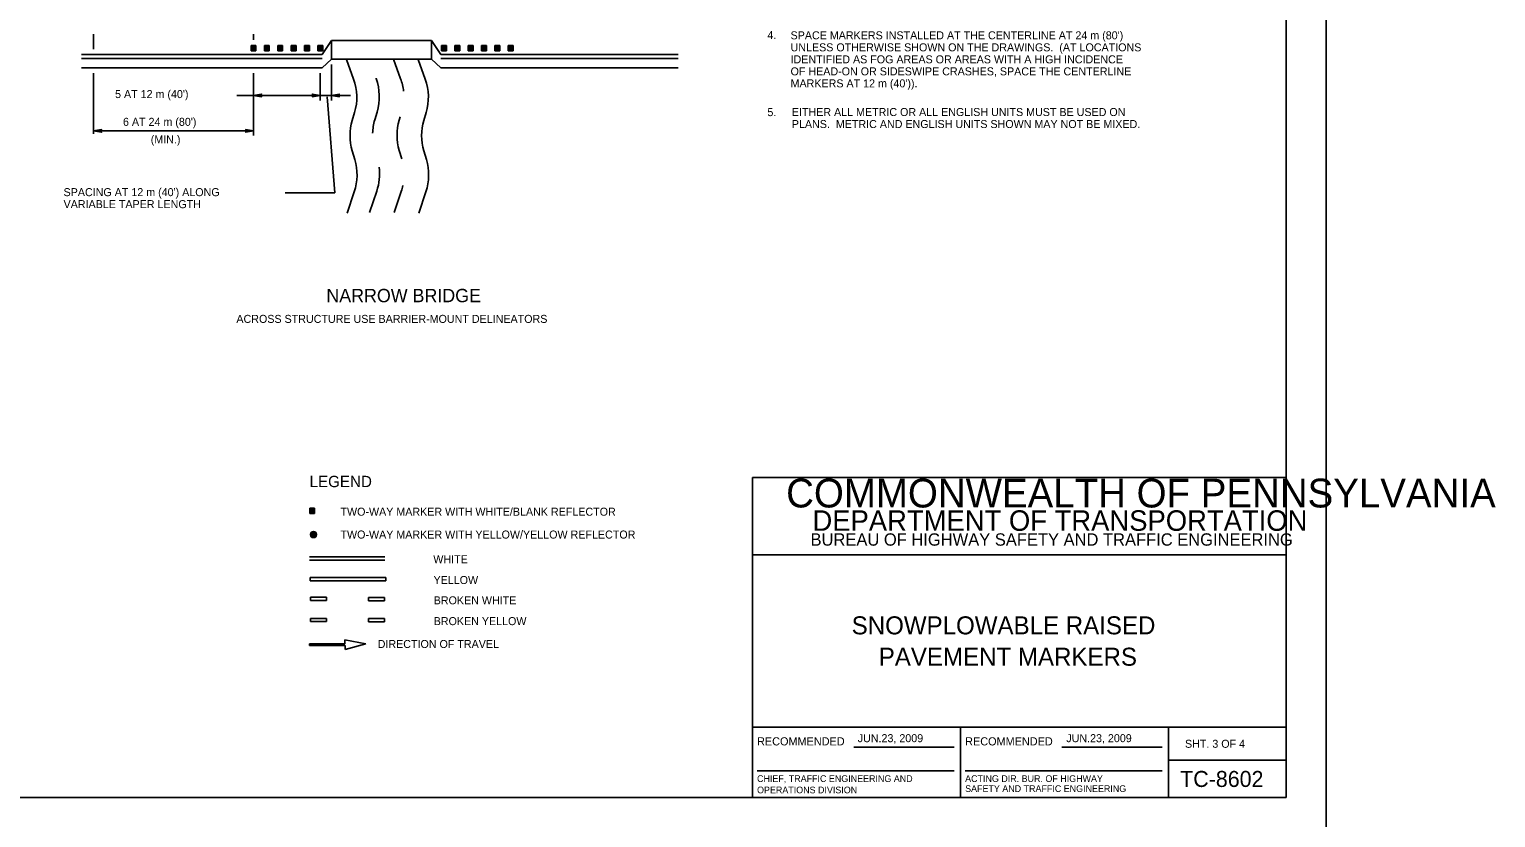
# Model space of a CAD drawing. Extents: x 639362 to 641108, y 298458 to 299646.
# Drawn here: x 640558 to 641108, y 299059 to 299355 of the extents above; entities that cross this region are included whole.
import ezdxf

# ---------------------------------------------------------------- set-up
doc = ezdxf.new("R2010")
doc.units = 0
for name, color, linetype in [('1', 7, 'Continuous'), ('2', 7, 'Continuous'), ('3', 7, 'Continuous'), ('PLT-BNDY', 7, 'Continuous')]:
    doc.layers.add(name, color=color, linetype=linetype)

# ---------------------------------------------------------------- blocks, each defined once
blk = doc.blocks.new('RARROW')
at = {"layer": '3'}
blk.add_lwpolyline([(-2.2695, 0.285), (-2.184875, 0.12075), (0, 0), (-2.2695, 0.285), (-2.38575, 0.384625), (0, 0), (-2.183125, -0.108), (-2.262875, -0.2705), (0, 0), (-2.38575, -0.379125), (-2.262875, -0.2705)], dxfattribs=at)

msp = doc.modelspace()

# ---------------------------------------------------------------- linework, layer by layer
at = {"layer": '1'}
for p, q in [((641029.31, 299066.63), (641029.31, 299630.63)), ((640829.31, 299066.63), (640829.31, 299186.63)), ((640829.31, 299186.63), (641029.31, 299186.63)), ((641029.31, 299157.63), (640829.31, 299157.63)), ((640829.31, 299093), (641029.31, 299093)), ((640907.31, 299093), (640907.31, 299066.63)), ((640985.19, 299066.63), (640985.19, 299093)), ((640867.24, 299085.57), (640904.87, 299085.57)), ((640945.24, 299085.57), (640982.87, 299085.57)), ((640985.19, 299080.63), (641029.31, 299080.63)), ((640830.99, 299076.68), (640904.87, 299076.68)), ((640908.99, 299076.68), (640982.87, 299076.68)), ((641029.31, 299066.63), (640243.31, 299066.63)), ((640243.31, 299066.63), (640829.31, 299066.63))]:
    msp.add_line(p, q, dxfattribs=at)
at = {"layer": '2'}
for p, q in [((640582.27, 299347.07), (640582.27, 299352.76)), ((640641.38, 299348.5), (640643.16, 299348.5)), ((640641.38, 299346.46), (640641.38, 299348.5)), ((640641.56, 299348.32), (640642.98, 299348.32)), ((640641.56, 299346.63), (640641.56, 299348.32)), ((640641.74, 299348.14), (640642.8, 299348.14)), ((640641.74, 299346.81), (640641.74, 299348.14)), ((640641.91, 299346.99), (640641.91, 299347.96)), ((640641.91, 299347.96), (640642.62, 299347.96)), ((640642.09, 299347.79), (640642.45, 299347.79)), ((640642.09, 299347.17), (640642.09, 299347.79)), ((640642.27, 299350.54), (640642.27, 299352.76)), ((640642.27, 299347.61), (640642.27, 299347.34)), ((640642.45, 299347.79), (640642.45, 299347.17)), ((640642.62, 299347.96), (640642.62, 299346.99)), ((640642.8, 299348.14), (640642.8, 299346.81)), ((640642.98, 299348.32), (640642.98, 299346.63)), ((640643.16, 299348.5), (640643.16, 299346.46)), ((640646.38, 299348.5), (640648.16, 299348.5)), ((640646.38, 299346.46), (640646.38, 299348.5)), ((640646.56, 299348.32), (640647.98, 299348.32)), ((640646.56, 299346.63), (640646.56, 299348.32)), ((640646.74, 299348.14), (640647.8, 299348.14)), ((640646.74, 299346.81), (640646.74, 299348.14)), ((640646.91, 299346.99), (640646.91, 299347.96)), ((640646.91, 299347.96), (640647.62, 299347.96)), ((640647.09, 299347.79), (640647.45, 299347.79)), ((640647.09, 299347.17), (640647.09, 299347.79)), ((640647.27, 299347.61), (640647.27, 299347.34)), ((640647.45, 299347.79), (640647.45, 299347.17)), ((640647.62, 299347.96), (640647.62, 299346.99)), ((640647.8, 299348.14), (640647.8, 299346.81)), ((640647.98, 299348.32), (640647.98, 299346.63)), ((640648.16, 299348.5), (640648.16, 299346.46)), ((640651.38, 299348.49), (640653.16, 299348.49)), ((640651.38, 299346.45), (640651.38, 299348.49)), ((640651.56, 299348.32), (640652.98, 299348.32)), ((640651.56, 299346.63), (640651.56, 299348.32)), ((640651.74, 299348.14), (640652.8, 299348.14)), ((640651.74, 299346.81), (640651.74, 299348.14)), ((640651.91, 299346.99), (640651.91, 299347.96)), ((640651.91, 299347.96), (640652.62, 299347.96)), ((640652.09, 299347.79), (640652.45, 299347.79)), ((640652.09, 299347.16), (640652.09, 299347.79)), ((640652.27, 299347.61), (640652.27, 299347.34)), ((640652.45, 299347.79), (640652.45, 299347.16)), ((640652.62, 299347.96), (640652.62, 299346.99)), ((640652.8, 299348.14), (640652.8, 299346.81)), ((640652.98, 299348.32), (640652.98, 299346.63)), ((640653.16, 299348.49), (640653.16, 299346.45)), ((640656.38, 299348.49), (640658.16, 299348.49)), ((640656.38, 299346.45), (640656.38, 299348.49)), ((640656.56, 299348.31), (640657.98, 299348.31)), ((640656.56, 299346.63), (640656.56, 299348.31)), ((640656.74, 299348.14), (640657.8, 299348.14)), ((640656.74, 299346.81), (640656.74, 299348.14)), ((640656.91, 299346.99), (640656.91, 299347.96)), ((640656.91, 299347.96), (640657.62, 299347.96)), ((640657.09, 299347.78), (640657.45, 299347.78)), ((640657.09, 299347.16), (640657.09, 299347.78)), ((640657.27, 299347.61), (640657.27, 299347.34)), ((640657.45, 299347.78), (640657.45, 299347.16)), ((640657.62, 299347.96), (640657.62, 299346.99)), ((640657.8, 299348.14), (640657.8, 299346.81)), ((640657.98, 299348.31), (640657.98, 299346.63)), ((640658.16, 299348.49), (640658.16, 299346.45)), ((640661.38, 299348.49), (640663.16, 299348.49)), ((640661.38, 299346.45), (640661.38, 299348.49)), ((640661.56, 299348.31), (640662.98, 299348.31)), ((640661.56, 299346.63), (640661.56, 299348.31)), ((640661.74, 299348.14), (640662.8, 299348.14)), ((640661.74, 299346.81), (640661.74, 299348.14)), ((640661.91, 299346.98), (640661.91, 299347.96)), ((640661.91, 299347.96), (640662.62, 299347.96)), ((640662.09, 299347.78), (640662.45, 299347.78)), ((640662.09, 299347.16), (640662.09, 299347.78)), ((640662.27, 299347.61), (640662.27, 299347.34)), ((640662.45, 299347.78), (640662.45, 299347.16)), ((640662.62, 299347.96), (640662.62, 299346.98)), ((640662.8, 299348.14), (640662.8, 299346.81)), ((640662.98, 299348.31), (640662.98, 299346.63)), ((640663.16, 299348.49), (640663.16, 299346.45)), ((640666.38, 299348.49), (640668.16, 299348.49)), ((640666.38, 299346.45), (640666.38, 299348.49)), ((640666.56, 299348.31), (640667.98, 299348.31)), ((640666.56, 299346.63), (640666.56, 299348.31)), ((640666.74, 299348.13), (640667.8, 299348.13)), ((640666.74, 299346.81), (640666.74, 299348.13)), ((640666.91, 299346.98), (640666.91, 299347.96)), ((640666.91, 299347.96), (640667.62, 299347.96)), ((640667.09, 299347.78), (640667.45, 299347.78)), ((640667.09, 299347.16), (640667.09, 299347.78)), ((640667.27, 299347.61), (640667.27, 299347.34)), ((640667.45, 299347.78), (640667.45, 299347.16)), ((640667.62, 299347.96), (640667.62, 299346.98)), ((640667.8, 299348.13), (640667.8, 299346.81)), ((640667.94, 299345.07), (640671.45, 299350.34)), ((640667.98, 299348.31), (640667.98, 299346.63)), ((640668.16, 299348.49), (640668.16, 299346.45)), ((640671.45, 299350.34), (640708.95, 299350.34)), ((640671.45, 299350.34), (640671.45, 299343.31)), ((640712.47, 299345.07), (640708.95, 299350.34)), ((640708.95, 299350.34), (640708.95, 299343.31)), ((640712.75, 299348.49), (640714.52, 299348.49)), ((640712.75, 299346.45), (640712.75, 299348.49)), ((640712.92, 299348.31), (640714.34, 299348.31)), ((640712.92, 299346.63), (640712.92, 299348.31)), ((640713.1, 299348.13), (640714.17, 299348.13)), ((640713.1, 299346.81), (640713.1, 299348.13)), ((640713.28, 299346.98), (640713.28, 299347.96)), ((640713.28, 299347.96), (640713.99, 299347.96)), ((640713.46, 299347.78), (640713.81, 299347.78)), ((640713.46, 299347.16), (640713.46, 299347.78)), ((640713.63, 299347.61), (640713.63, 299347.34)), ((640713.81, 299347.78), (640713.81, 299347.16)), ((640713.99, 299347.96), (640713.99, 299346.98)), ((640714.17, 299348.13), (640714.17, 299346.81)), ((640714.34, 299348.31), (640714.34, 299346.63)), ((640714.52, 299348.49), (640714.52, 299346.45)), ((640717.75, 299348.49), (640719.52, 299348.49)), ((640717.75, 299346.45), (640717.75, 299348.49)), ((640717.92, 299348.31), (640719.34, 299348.31)), ((640717.92, 299346.63), (640717.92, 299348.31)), ((640718.1, 299348.13), (640719.17, 299348.13)), ((640718.1, 299346.81), (640718.1, 299348.13)), ((640718.28, 299346.98), (640718.28, 299347.96)), ((640718.28, 299347.96), (640718.99, 299347.96)), ((640718.46, 299347.78), (640718.81, 299347.78)), ((640718.46, 299347.16), (640718.46, 299347.78)), ((640718.63, 299347.6), (640718.63, 299347.34)), ((640718.81, 299347.78), (640718.81, 299347.16)), ((640718.99, 299347.96), (640718.99, 299346.98)), ((640719.17, 299348.13), (640719.17, 299346.81)), ((640719.34, 299348.31), (640719.34, 299346.63)), ((640719.52, 299348.49), (640719.52, 299346.45)), ((640722.75, 299348.49), (640724.52, 299348.49)), ((640722.75, 299346.45), (640722.75, 299348.49)), ((640722.92, 299348.31), (640724.34, 299348.31)), ((640722.92, 299346.63), (640722.92, 299348.31)), ((640723.1, 299348.13), (640724.17, 299348.13)), ((640723.1, 299346.8), (640723.1, 299348.13)), ((640723.28, 299346.98), (640723.28, 299347.96)), ((640723.28, 299347.96), (640723.99, 299347.96)), ((640723.46, 299347.78), (640723.81, 299347.78)), ((640723.46, 299347.16), (640723.46, 299347.78)), ((640723.63, 299347.6), (640723.63, 299347.33)), ((640723.81, 299347.78), (640723.81, 299347.16)), ((640723.99, 299347.96), (640723.99, 299346.98)), ((640724.17, 299348.13), (640724.17, 299346.8)), ((640724.34, 299348.31), (640724.34, 299346.63)), ((640724.52, 299348.49), (640724.52, 299346.45)), ((640727.75, 299348.49), (640729.52, 299348.49)), ((640727.75, 299346.45), (640727.75, 299348.49)), ((640727.92, 299348.31), (640729.34, 299348.31)), ((640727.92, 299346.62), (640727.92, 299348.31)), ((640728.1, 299348.13), (640729.17, 299348.13)), ((640728.1, 299346.8), (640728.1, 299348.13)), ((640728.28, 299346.98), (640728.28, 299347.95)), ((640728.28, 299347.95), (640728.99, 299347.95)), ((640728.46, 299347.78), (640728.81, 299347.78)), ((640728.46, 299347.16), (640728.46, 299347.78)), ((640728.63, 299347.6), (640728.63, 299347.33)), ((640728.81, 299347.78), (640728.81, 299347.16)), ((640728.99, 299347.95), (640728.99, 299346.98)), ((640729.17, 299348.13), (640729.17, 299346.8)), ((640729.34, 299348.31), (640729.34, 299346.62)), ((640729.52, 299348.49), (640729.52, 299346.45)), ((640732.75, 299348.49), (640734.52, 299348.49)), ((640732.75, 299346.45), (640732.75, 299348.49)), ((640732.92, 299348.31), (640734.34, 299348.31)), ((640732.92, 299346.62), (640732.92, 299348.31)), ((640733.1, 299348.13), (640734.17, 299348.13)), ((640733.1, 299346.8), (640733.1, 299348.13)), ((640733.28, 299346.98), (640733.28, 299347.95)), ((640733.28, 299347.95), (640733.99, 299347.95)), ((640733.46, 299347.78), (640733.81, 299347.78)), ((640733.46, 299347.16), (640733.46, 299347.78)), ((640733.63, 299347.6), (640733.63, 299347.33)), ((640733.81, 299347.78), (640733.81, 299347.16)), ((640733.99, 299347.95), (640733.99, 299346.98)), ((640734.17, 299348.13), (640734.17, 299346.8)), ((640734.34, 299348.31), (640734.34, 299346.62)), ((640734.52, 299348.49), (640734.52, 299346.45)), ((640737.75, 299348.48), (640739.52, 299348.48)), ((640737.75, 299346.44), (640737.75, 299348.48)), ((640737.92, 299348.31), (640739.34, 299348.31)), ((640737.92, 299346.62), (640737.92, 299348.31)), ((640738.1, 299348.13), (640739.17, 299348.13)), ((640738.1, 299346.8), (640738.1, 299348.13)), ((640738.28, 299346.98), (640738.28, 299347.95)), ((640738.28, 299347.95), (640738.99, 299347.95)), ((640738.46, 299347.78), (640738.81, 299347.78)), ((640738.46, 299347.15), (640738.46, 299347.78)), ((640738.63, 299347.6), (640738.63, 299347.33)), ((640738.81, 299347.78), (640738.81, 299347.15)), ((640738.99, 299347.95), (640738.99, 299346.98)), ((640739.17, 299348.13), (640739.17, 299346.8)), ((640739.34, 299348.31), (640739.34, 299346.62)), ((640739.52, 299348.48), (640739.52, 299346.44)), ((640577.74, 299345.07), (640667.94, 299345.07)), ((640577.74, 299343.57), (640667.94, 299343.57)), ((640643.16, 299346.46), (640641.38, 299346.46)), ((640642.98, 299346.63), (640641.56, 299346.63)), ((640642.8, 299346.81), (640641.74, 299346.81)), ((640642.62, 299346.99), (640641.91, 299346.99)), ((640642.45, 299347.17), (640642.09, 299347.17)), ((640648.16, 299346.46), (640646.38, 299346.46)), ((640647.98, 299346.63), (640646.56, 299346.63)), ((640647.8, 299346.81), (640646.74, 299346.81)), ((640647.62, 299346.99), (640646.91, 299346.99)), ((640647.45, 299347.17), (640647.09, 299347.17)), ((640653.16, 299346.45), (640651.38, 299346.45)), ((640652.98, 299346.63), (640651.56, 299346.63)), ((640652.8, 299346.81), (640651.74, 299346.81)), ((640652.62, 299346.99), (640651.91, 299346.99)), ((640652.45, 299347.16), (640652.09, 299347.16)), ((640658.16, 299346.45), (640656.38, 299346.45)), ((640657.98, 299346.63), (640656.56, 299346.63)), ((640657.8, 299346.81), (640656.74, 299346.81)), ((640657.62, 299346.99), (640656.91, 299346.99)), ((640657.45, 299347.16), (640657.09, 299347.16)), ((640663.16, 299346.45), (640661.38, 299346.45)), ((640662.98, 299346.63), (640661.56, 299346.63)), ((640662.8, 299346.81), (640661.74, 299346.81)), ((640662.62, 299346.98), (640661.91, 299346.98)), ((640662.45, 299347.16), (640662.09, 299347.16)), ((640668.16, 299346.45), (640666.38, 299346.45)), ((640667.98, 299346.63), (640666.56, 299346.63)), ((640667.8, 299346.81), (640666.74, 299346.81)), ((640667.62, 299346.98), (640666.91, 299346.98)), ((640667.45, 299347.16), (640667.09, 299347.16)), ((640667.94, 299340.07), (640671.45, 299343.31)), ((640671.45, 299343.31), (640708.95, 299343.31)), ((640679.74, 299335.87), (640677.07, 299343.23)), ((640697.39, 299336.02), (640694.71, 299343.37)), ((640706.59, 299335.87), (640703.91, 299343.23)), ((640712.47, 299340.07), (640708.95, 299343.31)), ((640712.47, 299345.07), (640801.44, 299345.07)), ((640712.47, 299343.57), (640801.44, 299343.57)), ((640714.52, 299346.45), (640712.75, 299346.45)), ((640714.34, 299346.63), (640712.92, 299346.63)), ((640714.17, 299346.81), (640713.1, 299346.81)), ((640713.99, 299346.98), (640713.28, 299346.98)), ((640713.81, 299347.16), (640713.46, 299347.16)), ((640719.52, 299346.45), (640717.75, 299346.45)), ((640719.34, 299346.63), (640717.92, 299346.63)), ((640719.17, 299346.81), (640718.1, 299346.81)), ((640718.99, 299346.98), (640718.28, 299346.98)), ((640718.81, 299347.16), (640718.46, 299347.16)), ((640724.52, 299346.45), (640722.75, 299346.45)), ((640724.34, 299346.63), (640722.92, 299346.63)), ((640724.17, 299346.8), (640723.1, 299346.8)), ((640723.99, 299346.98), (640723.28, 299346.98)), ((640723.81, 299347.16), (640723.46, 299347.16)), ((640729.52, 299346.45), (640727.75, 299346.45)), ((640729.34, 299346.62), (640727.92, 299346.62)), ((640729.17, 299346.8), (640728.1, 299346.8)), ((640728.99, 299346.98), (640728.28, 299346.98)), ((640728.81, 299347.16), (640728.46, 299347.16)), ((640734.52, 299346.45), (640732.75, 299346.45)), ((640734.34, 299346.62), (640732.92, 299346.62)), ((640734.17, 299346.8), (640733.1, 299346.8)), ((640733.99, 299346.98), (640733.28, 299346.98)), ((640733.81, 299347.16), (640733.46, 299347.16)), ((640739.52, 299346.44), (640737.75, 299346.44)), ((640739.34, 299346.62), (640737.92, 299346.62)), ((640739.17, 299346.8), (640738.1, 299346.8)), ((640738.99, 299346.98), (640738.28, 299346.98)), ((640738.81, 299347.15), (640738.46, 299347.15)), ((640577.74, 299340.07), (640667.94, 299340.07)), ((640582.26, 299315.37), (640582.26, 299338.07)), ((640642.26, 299314.79), (640642.26, 299338.07)), ((640667.26, 299327.81), (640667.26, 299338.07)), ((640671.45, 299327.8), (640671.45, 299341.31)), ((640712.47, 299340.07), (640801.44, 299340.07)), ((640688.19, 299336.08), (640688.16, 299336.16)), ((640667.26, 299329.77), (640635.98, 299329.77)), ((640678.56, 299329.77), (640667.26, 299329.77)), ((640672.76, 299293.3), (640669.79, 299329.18)), ((640679.24, 299320.39), (640680.12, 299323.32)), ((640687.68, 299320.6), (640688.56, 299323.54)), ((640696.89, 299320.54), (640697.23, 299321.69)), ((640706.09, 299320.39), (640706.96, 299323.32)), ((640642.26, 299316.45), (640582.26, 299316.46)), ((640680.21, 299305.72), (640679.23, 299309)), ((640697.82, 299305.96), (640696.88, 299309.14)), ((640707.05, 299305.72), (640706.08, 299309)), ((640672.76, 299293.3), (640654.16, 299293.3)), ((640677.31, 299285.68), (640679.99, 299293.67)), ((640685.75, 299285.9), (640688.43, 299293.88)), ((640694.95, 299285.83), (640697.63, 299293.81)), ((640704.15, 299285.68), (640706.83, 299293.67)), ((640663.35, 299175.09), (640665.13, 299175.09)), ((640663.35, 299173.05), (640663.35, 299175.09)), ((640665.13, 299173.05), (640663.35, 299173.05)), ((640663.53, 299174.91), (640664.95, 299174.91)), ((640663.53, 299173.22), (640663.53, 299174.91)), ((640664.95, 299173.22), (640663.53, 299173.22)), ((640663.71, 299174.73), (640664.77, 299174.73)), ((640663.71, 299173.4), (640663.71, 299174.73)), ((640664.77, 299173.4), (640663.71, 299173.4)), ((640663.89, 299173.58), (640663.89, 299174.55)), ((640663.89, 299174.55), (640664.59, 299174.55)), ((640664.59, 299173.58), (640663.89, 299173.58)), ((640664.06, 299174.38), (640664.42, 299174.38)), ((640664.06, 299173.76), (640664.06, 299174.38)), ((640664.42, 299173.76), (640664.06, 299173.76)), ((640664.24, 299174.2), (640664.24, 299173.93)), ((640664.42, 299174.38), (640664.42, 299173.76)), ((640664.59, 299174.55), (640664.59, 299173.58)), ((640664.77, 299174.73), (640664.77, 299173.4)), ((640664.95, 299174.91), (640664.95, 299173.22)), ((640665.13, 299175.09), (640665.13, 299173.05)), ((640691.51, 299156.85), (640663.23, 299156.85)), ((640691.51, 299155.65), (640663.23, 299155.65)), ((640691.78, 299149.09), (640663.5, 299149.09)), ((640663.5, 299149.09), (640663.5, 299147.89)), ((640663.5, 299147.89), (640691.78, 299147.89)), ((640691.78, 299147.89), (640691.78, 299149.09)), ((640669.6, 299141.71), (640663.58, 299141.71)), ((640663.58, 299141.71), (640663.58, 299140.51)), ((640663.58, 299140.51), (640669.6, 299140.51)), ((640669.6, 299140.51), (640669.6, 299141.71)), ((640691.32, 299141.61), (640685.3, 299141.61)), ((640685.3, 299141.61), (640685.3, 299140.41)), ((640685.3, 299140.41), (640691.32, 299140.41)), ((640691.32, 299140.41), (640691.32, 299141.61)), ((640663.61, 299133.81), (640663.61, 299132.61)), ((640669.62, 299133.81), (640663.61, 299133.81)), ((640669.62, 299132.61), (640669.62, 299133.81)), ((640685.33, 299133.71), (640685.33, 299132.51)), ((640691.34, 299133.71), (640685.33, 299133.71)), ((640691.34, 299132.51), (640691.34, 299133.71)), ((640663.61, 299132.61), (640669.62, 299132.61)), ((640685.33, 299132.51), (640691.34, 299132.51)), ((640676.5, 299124.3), (640663.26, 299124.3)), ((640663.26, 299124.3), (640663.26, 299123.59)), ((640663.26, 299123.59), (640676.58, 299123.59)), ((640684.31, 299124.26), (640676.5, 299125.74)), ((640676.5, 299125.74), (640676.5, 299124.3)), ((640676.58, 299122.15), (640684.31, 299124.26)), ((640676.58, 299123.59), (640676.58, 299122.15))]:
    msp.add_line(p, q, dxfattribs=at)
for radius in [1.15, 1.07, 0.985, 0.904, 0.822, 0.741, 0.659, 0.578, 0.496, 0.414, 0.333, 0.251, 0.17, 0.0881]:
    msp.add_circle((640664.72, 299165.21), radius, dxfattribs=at)
for centre, start, end in [((640660.95, 299329.03), 343.4142, 19.9879), ((640669.39, 299329.25), 343.4142, 19.9879), ((640678.59, 299329.18), 6.1927, 19.9879), ((640687.79, 299329.03), 343.4142, 19.9879), ((640698.41, 299314.68), 163.4142, 196.5084), ((640706.85, 299314.89), 163.4142, 177.785), ((640716.05, 299314.83), 163.4142, 196.5084), ((640725.26, 299314.68), 163.4142, 196.5084), ((640661.03, 299300.04), 341.4259, 16.5084), ((640687.88, 299300.04), 341.4259, 16.5084), ((640669.47, 299300.25), 341.4259, 7.3864), ((640678.67, 299300.18), 341.4259, 347.8196)]:
    msp.add_arc(centre, 20, start, end, dxfattribs=at)
at = {"layer": 'PLT-BNDY'}
msp.add_lwpolyline([(640203.31, 299645.63), (641044.31, 299645.63), (641044.31, 299051.63), (640203.31, 299051.63)], close=True, dxfattribs=at)

# ---------------------------------------------------------------- block references
at = {"layer": '2', "xscale": 1.2574347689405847, "yscale": 1.3092961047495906, "rotation": 180}
for p in [(640642.26, 299329.77), (640671.45, 299329.77), (640582.26, 299316.46)]:
    msp.add_blockref('RARROW', p, dxfattribs=at)
at = {"layer": '2', "xscale": 1.2574347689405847, "yscale": 1.3092961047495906}
for p in [(640667.26, 299329.77), (640642.26, 299316.45)]:
    msp.add_blockref('RARROW', p, dxfattribs=at)

# ---------------------------------------------------------------- texts
at = {"layer": '1'}
for s, height, p in [('COMMONWEALTH OF PENNSYLVANIA', 10.7828, (640841.9, 299175.36)), ('DEPARTMENT OF TRANSPORTATION', 7.6837, (640851.76, 299166.61)), ('BUREAU OF HIGHWAY SAFETY AND TRAFFIC ENGINEERING', 4.6253, (640851.04, 299161.04)), ('SNOWPLOWABLE RAISED', 6.75, (640866.46, 299127.81)), ('PAVEMENT MARKERS', 6.75, (640876.61, 299116.06)), ('RECOMMENDED', 3.048, (640830.99, 299086.2)), ('RECOMMENDED', 3.048, (640908.99, 299086.2)), ('SHT. 3 OF 4', 3, (640991.4, 299085.31)), ('CHIEF, TRAFFIC ENGINEERING AND', 2.5, (640830.99, 299072.51)), ('ACTING DIR. BUR. OF HIGHWAY', 2.5, (640908.99, 299072.51)), ('TC-8602', 6, (640989.6, 299070.63)), ('OPERATIONS DIVISION', 2.5, (640830.99, 299068.26)), ('SAFETY AND TRAFFIC ENGINEERING', 2.5, (640908.99, 299068.76))]:
    msp.add_text(s, height=height, dxfattribs=at).set_placement(p)
for p in [(640868.72, 299087.41), (640946.91, 299087.41)]:
    msp.add_text('JUN.23, 2009', height=3, rotation=360, dxfattribs=at).set_placement(p)
at = {"layer": '2'}
for s, height, p in [('4. ', 3, (640834.87, 299350.89)), ("SPACE MARKERS INSTALLED AT THE CENTERLINE AT 24 m (80')", 3, (640843.55, 299350.77)), ('UNLESS OTHERWISE SHOWN ON THE DRAWINGS.  (AT LOCATIONS', 3, (640843.55, 299346.27)), ('IDENTIFIED AS FOG AREAS OR AREAS WITH A HIGH INCIDENCE', 3, (640843.55, 299341.77)), ('OF HEAD-ON OR SIDESWIPE CRASHES, SPACE THE CENTERLINE', 3, (640843.55, 299337.27)), ("5 AT 12 m (40')", 3, (640590.34, 299328.76)), ("MARKERS AT 12 m (40')).", 3, (640843.55, 299332.77)), ("6 AT 24 m (80')", 3, (640593.31, 299318.36)), ('5. ', 3, (640834.87, 299322)), ('EITHER ALL METRIC OR ALL ENGLISH UNITS MUST BE USED ON', 3, (640844.02, 299322.03)), ('PLANS.  METRIC AND ENGLISH UNITS SHOWN MAY NOT BE MIXED.', 3, (640844.02, 299317.53)), (' (MIN.)', 3, (640602.6, 299311.77)), ("SPACING AT 12 m (40') ALONG", 3, (640571.03, 299292.01)), ('VARIABLE TAPER LENGTH', 3, (640571.03, 299287.51)), ('NARROW BRIDGE', 5, (640669.54, 299252.27)), ('ACROSS STRUCTURE USE BARRIER-MOUNT DELINEATORS', 3, (640635.82, 299244.52)), ('LEGEND', 4.25, (640663.25, 299182.97)), ('TWO-WAY MARKER WITH WHITE/BLANK REFLECTOR', 3, (640674.83, 299172.27)), ('WHITE', 3, (640709.63, 299154.47)), ('YELLOW', 3, (640709.71, 299146.67)), ('BROKEN WHITE', 3, (640709.78, 299139.06)), ('BROKEN YELLOW', 3, (640709.78, 299131.27)), ('DIRECTION OF TRAVEL', 3, (640688.78, 299122.7))]:
    msp.add_text(s, height=height, dxfattribs=at).set_placement(p)
msp.add_text('TWO-WAY MARKER WITH YELLOW/YELLOW REFLECTOR', height=3, rotation=360, dxfattribs=at).set_placement((640674.83, 299163.71))

doc.saveas('drawing.dxf')
